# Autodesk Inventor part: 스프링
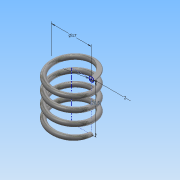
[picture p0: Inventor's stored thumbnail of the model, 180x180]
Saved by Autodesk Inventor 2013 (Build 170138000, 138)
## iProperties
Created: 2017-07
Part Number: 스프링
Material: 스테인리스강
Document SubType Name: Modeling
Designer: Administrator
Mass: 5.32128 g
Surface Area: 13.3957 cm^2
Volume: 0.658575 cm^3
Density: 8.08 g/cm^3
Author: Administrator
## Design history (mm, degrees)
sketch "스케치2"
  geometry: L1 (0, 0)-(-8.5, 0); L2 (-8.5, 0)-(-8.5, -20.5); L3 (-8.5, -20.5)-(0, -20.5); L4 (0, -20.5)-(0, 0); C1 r 1 at (-8.5, 0)
  constraints: 8 end point, 2 parallel, 1 centre point, 1 coincident, 1 horizontal, 1 perpendicular
  dimensions: "d0" = 2 diameter of C1; "d2" = 20.5 distance of L1.end L2.end (derived); "d3" = 17 diameter of L2 L4
feature "코일1" pitch "d4" = 10; turns "d6" = 4; dims "d5" = 20.5 (= d2), "d7" = 0, angle "d8" = 90 deg, angle "d9" = 90 deg, "d10" = 0, "d11" = 0
sketch "스케치3"
  geometry: L1 (9.5, 0)-(7.5, 0) reference; 1 further point
  constraints: 1 horizontal alignment
extrude "돌출1" cut sketch "스케치3" stored distance "d12" = 10; taper "d13" = 0 deg
node "작업 평면1"
sketch "스케치4"
  geometry: L1 (-1, 0)-(1, 0) reference; 1 further point
  constraints: 1 horizontal alignment
extrude "돌출2" cut sketch "스케치4" stored distance "d15" = 10; taper "d16" = 0 deg
node "솔리드1"
node "절단 모서리 투영1"
node "절단 모서리 투영2"
other parameters: "d14" = 90 deg
